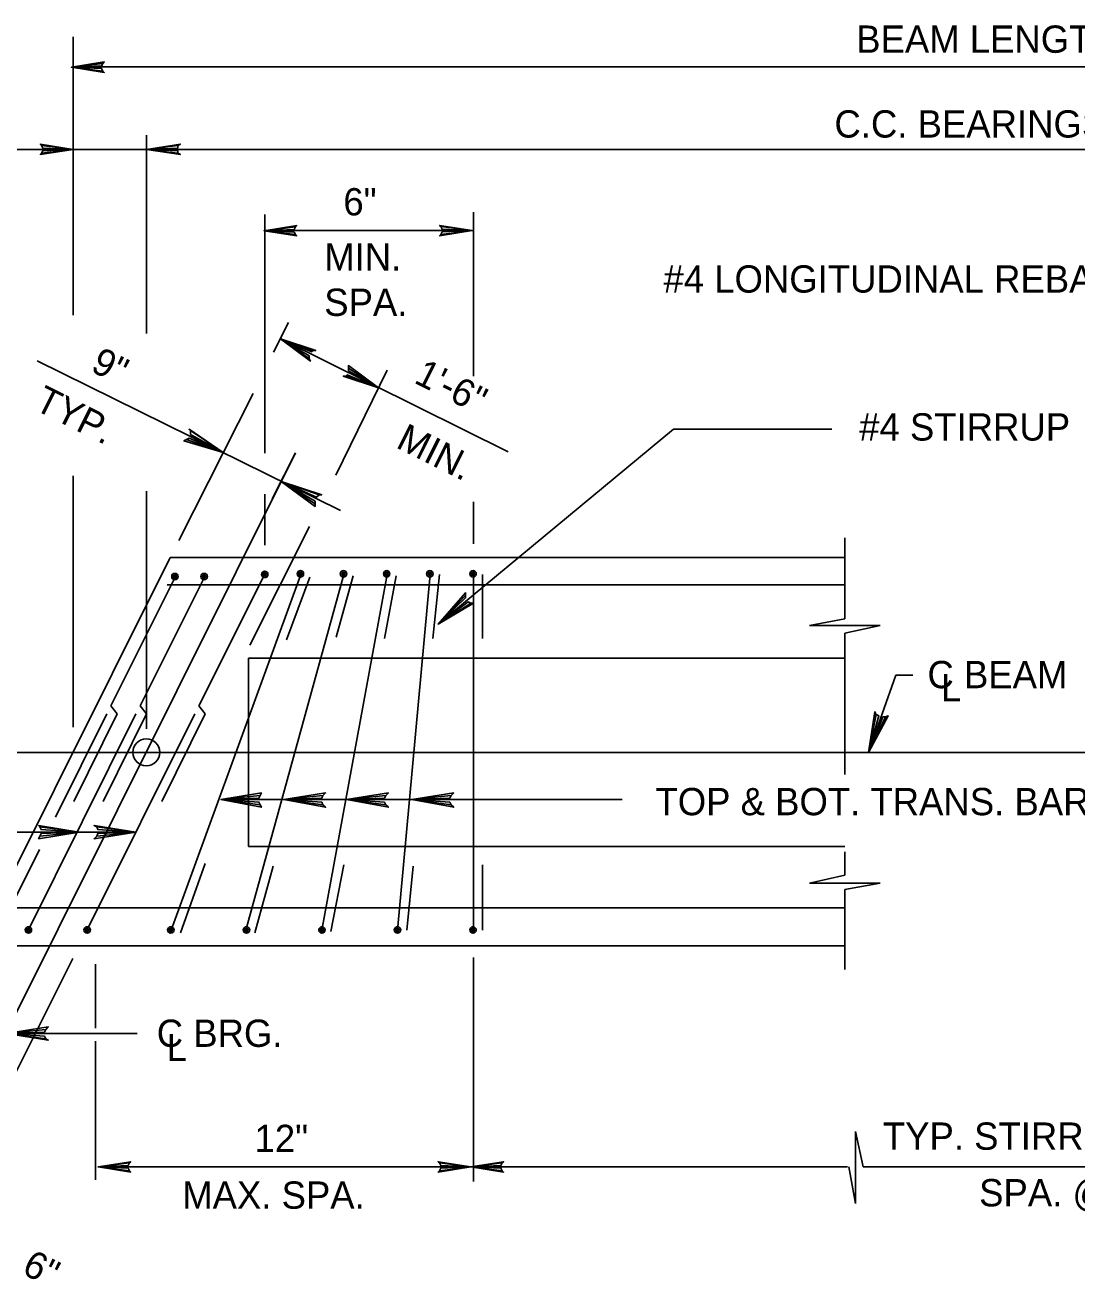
# Model space of a CAD drawing. Extents: x 642009 to 642864, y 298232 to 300014.
# Drawn here: x 642566 to 642681.6, y 299703.5 to 299841.4 of the extents above; entities that cross this region are included whole.
import ezdxf

# ---------------------------------------------------------------- set-up
doc = ezdxf.new("R2010")
doc.units = 0
doc.layers.add('2', color=7, linetype='Continuous')

msp = doc.modelspace()

# ---------------------------------------------------------------- linework, layer by layer
at = {"layer": '2'}
for p, q in [((642571.23, 299840.13), (642571.23, 299809.55)), ((642571.23, 299836.82), (642772.99, 299836.82)), ((642579.29, 299829.34), (642579.29, 299807.53)), ((642533.37, 299827.76), (642571.96, 299827.76)), ((642571.96, 299827.76), (642579.29, 299827.76)), ((642579.29, 299827.76), (642763.44, 299827.76)), ((642592.3, 299794.39), (642592.3, 299820.59)), ((642615.23, 299802.83), (642615.23, 299820.85)), ((642592.3, 299818.83), (642615.11, 299818.83)), ((642593.27, 299805.46), (642594.91, 299808.72)), ((642594.02, 299806.95), (642619.04, 299794.51)), ((642567.3, 299804.54), (642589.79, 299793.41)), ((642600.11, 299791.95), (642605.77, 299803.51)), ((642582.85, 299784.77), (642591.02, 299800.94)), ((642637.23, 299797), (642611.35, 299775.58)), ((642654.61, 299797), (642637.23, 299797)), ((642563.05, 299729.01), (642595.68, 299794.41)), ((642593.13, 299789.35), (642595.68, 299794.41)), ((642589.79, 299793.41), (642600.63, 299788.07)), ((642571.23, 299791.88), (642571.23, 299764.25)), ((642594.1, 299791.25), (642597.69, 299789.53)), ((642579.29, 299790.2), (642579.29, 299764.09)), ((642592.3, 299784.25), (642592.3, 299789.85)), ((642597.69, 299790.1), (642597.69, 299790.1)), ((642615.23, 299784.4), (642615.23, 299789.04)), ((642590.65, 299773.28), (642597.23, 299786.33)), ((642656.06, 299776.16), (642656.06, 299785.07)), ((642560.61, 299740.22), (642581.91, 299782.91)), ((642656.06, 299782.91), (642581.91, 299782.91)), ((642582.46, 299780.75), (642575.39, 299766.59)), ((642585.68, 299780.75), (642578.61, 299766.59)), ((642596.26, 299781.04), (642582.03, 299741.94)), ((642582.46, 299780.75), (642582.46, 299780.75)), ((642582.46, 299780.75), (642582.46, 299780.75)), ((642592.27, 299781.01), (642585.07, 299766.59)), ((642585.68, 299780.75), (642585.68, 299780.75)), ((642585.68, 299780.75), (642585.68, 299780.75)), ((642601, 299781.04), (642590.22, 299741.94)), ((642592.33, 299780.99), (642592.33, 299780.99)), ((642592.33, 299780.99), (642592.33, 299780.99)), ((642597.26, 299780.76), (642594.68, 299773.86)), ((642596.26, 299781.04), (642596.26, 299781.04)), ((642596.26, 299781.04), (642596.26, 299781.04)), ((642596.26, 299781.04), (642596.26, 299781.04)), ((642605.74, 299781.04), (642598.56, 299741.94)), ((642602.01, 299780.9), (642600.14, 299774.14)), ((642601, 299781.04), (642601, 299781.04)), ((642601, 299781.04), (642601, 299781.04)), ((642601, 299781.04), (642601, 299781.04)), ((642601, 299781.04), (642601, 299781.04)), ((642606.75, 299780.9), (642605.46, 299774)), ((642605.74, 299781.04), (642605.74, 299781.04)), ((642605.74, 299781.04), (642605.74, 299781.04)), ((642605.74, 299781.04), (642605.74, 299781.04)), ((642605.74, 299781.04), (642605.74, 299781.04)), ((642605.74, 299781.04), (642605.74, 299781.04)), ((642610.49, 299781.04), (642606.89, 299741.94)), ((642610.49, 299781.04), (642610.49, 299781.04)), ((642610.49, 299781.04), (642610.49, 299781.04)), ((642610.49, 299781.04), (642610.49, 299781.04)), ((642610.49, 299781.04), (642610.49, 299781.04)), ((642610.49, 299781.04), (642610.49, 299781.04)), ((642610.49, 299781.04), (642610.49, 299781.04)), ((642611.49, 299781.04), (642610.78, 299774)), ((642615.23, 299741.94), (642615.23, 299781.04)), ((642615.23, 299781.04), (642615.23, 299781.04)), ((642615.23, 299781.04), (642615.23, 299781.04)), ((642615.23, 299781.04), (642615.23, 299781.04)), ((642615.23, 299781.04), (642615.23, 299781.04)), ((642615.23, 299781.04), (642615.23, 299781.04)), ((642615.23, 299781.04), (642615.23, 299781.04)), ((642615.23, 299781.04), (642615.23, 299781.04)), ((642616.24, 299774), (642616.24, 299781.04)), ((642656.06, 299779.89), (642581.59, 299779.89)), ((642656.06, 299776.16), (642652.18, 299775.44)), ((642659.94, 299775.44), (642652.18, 299775.44)), ((642659.94, 299775.44), (642656.06, 299774.58)), ((642656.06, 299759.05), (642656.06, 299774.58)), ((642656.06, 299771.84), (642590.51, 299771.84)), ((642590.51, 299751.14), (642590.51, 299771.84)), ((642661.66, 299769.98), (642658.64, 299761.49)), ((642663.53, 299769.98), (642661.66, 299769.98)), ((642575.39, 299766.59), (642576.08, 299765.71)), ((642578.61, 299766.59), (642579.3, 299765.71)), ((642585.07, 299766.59), (642585.76, 299765.71)), ((642578.15, 299765.72), (642566.33, 299741.97)), ((642574.93, 299765.72), (642569.29, 299754.37)), ((642576.08, 299765.71), (642571.32, 299756.08)), ((642584.61, 299765.72), (642572.79, 299741.97)), ((642579.3, 299765.71), (642574.53, 299756.08)), ((642585.76, 299765.71), (642580.99, 299756.08)), ((642671.29, 299761.49), (642563.68, 299761.49)), ((642571.96, 299761.49), (642571.96, 299761.49)), ((642579.29, 299761.49), (642579.29, 299761.49)), ((642671.29, 299761.49), (642791.33, 299761.49)), ((642594.39, 299756.32), (642587.49, 299756.32)), ((642601.29, 299756.32), (642594.39, 299756.32)), ((642608.48, 299756.32), (642601.29, 299756.32)), ((642615.38, 299756.32), (642608.48, 299756.32)), ((642631.57, 299756.32), (642615.38, 299756.32)), ((642577.71, 299752.72), (642530.85, 299752.72)), ((642567.53, 299750.83), (642563.12, 299741.97)), ((642656.06, 299751.14), (642590.51, 299751.14)), ((642656.06, 299747.98), (642656.06, 299750.57)), ((642585.76, 299749.28), (642583.03, 299741.66)), ((642593.24, 299748.99), (642591.23, 299741.66)), ((642601, 299749.13), (642599.56, 299741.8)), ((642608.62, 299748.99), (642607.9, 299741.94)), ((642616.24, 299741.94), (642616.24, 299749.13)), ((642656.06, 299747.98), (642652.18, 299747.12)), ((642659.94, 299747.12), (642652.18, 299747.12)), ((642659.94, 299747.12), (642656.06, 299746.4)), ((642656.06, 299737.63), (642656.06, 299746.4)), ((642656.06, 299744.39), (642563.78, 299744.39)), ((642566.33, 299741.94), (642566.33, 299741.94)), ((642566.33, 299741.94), (642566.33, 299741.94)), ((642566.33, 299741.94), (642566.33, 299741.94)), ((642566.33, 299741.94), (642566.33, 299741.94)), ((642566.33, 299741.94), (642566.33, 299741.94)), ((642566.33, 299741.94), (642566.33, 299741.94)), ((642566.33, 299741.94), (642566.33, 299741.94)), ((642566.33, 299741.94), (642566.33, 299741.94)), ((642566.33, 299741.94), (642566.33, 299741.94)), ((642566.33, 299741.94), (642566.33, 299741.94)), ((642566.33, 299741.94), (642566.33, 299741.94)), ((642566.33, 299741.94), (642566.33, 299741.94)), ((642566.33, 299741.94), (642566.33, 299741.94)), ((642572.79, 299741.94), (642572.79, 299741.94)), ((642572.79, 299741.94), (642572.79, 299741.94)), ((642572.79, 299741.94), (642572.79, 299741.94)), ((642572.79, 299741.94), (642572.79, 299741.94)), ((642572.79, 299741.94), (642572.79, 299741.94)), ((642572.79, 299741.94), (642572.79, 299741.94)), ((642572.79, 299741.94), (642572.79, 299741.94)), ((642572.79, 299741.94), (642572.79, 299741.94)), ((642572.79, 299741.94), (642572.79, 299741.94)), ((642572.79, 299741.94), (642572.79, 299741.94)), ((642572.79, 299741.94), (642572.79, 299741.94)), ((642572.79, 299741.94), (642572.79, 299741.94)), ((642572.79, 299741.94), (642572.79, 299741.94)), ((642582.03, 299741.94), (642582.03, 299741.94)), ((642582.03, 299741.94), (642582.03, 299741.94)), ((642582.03, 299741.94), (642582.03, 299741.94)), ((642582.03, 299741.94), (642582.03, 299741.94)), ((642582.03, 299741.94), (642582.03, 299741.94)), ((642582.03, 299741.94), (642582.03, 299741.94)), ((642582.03, 299741.94), (642582.03, 299741.94)), ((642582.03, 299741.94), (642582.03, 299741.94)), ((642582.03, 299741.94), (642582.03, 299741.94)), ((642582.03, 299741.94), (642582.03, 299741.94)), ((642582.03, 299741.94), (642582.03, 299741.94)), ((642582.03, 299741.94), (642582.03, 299741.94)), ((642590.22, 299741.94), (642590.22, 299741.94)), ((642590.22, 299741.94), (642590.22, 299741.94)), ((642590.22, 299741.94), (642590.22, 299741.94)), ((642590.22, 299741.94), (642590.22, 299741.94)), ((642590.22, 299741.94), (642590.22, 299741.94)), ((642590.22, 299741.94), (642590.22, 299741.94)), ((642590.22, 299741.94), (642590.22, 299741.94)), ((642590.22, 299741.94), (642590.22, 299741.94)), ((642590.22, 299741.94), (642590.22, 299741.94)), ((642590.22, 299741.94), (642590.22, 299741.94)), ((642590.22, 299741.94), (642590.22, 299741.94)), ((642598.56, 299741.94), (642598.56, 299741.94)), ((642598.56, 299741.94), (642598.56, 299741.94)), ((642598.56, 299741.94), (642598.56, 299741.94)), ((642598.56, 299741.94), (642598.56, 299741.94)), ((642598.56, 299741.94), (642598.56, 299741.94)), ((642598.56, 299741.94), (642598.56, 299741.94)), ((642598.56, 299741.94), (642598.56, 299741.94)), ((642598.56, 299741.94), (642598.56, 299741.94)), ((642598.56, 299741.94), (642598.56, 299741.94)), ((642598.56, 299741.94), (642598.56, 299741.94)), ((642606.89, 299741.94), (642606.89, 299741.94)), ((642606.89, 299741.94), (642606.89, 299741.94)), ((642606.89, 299741.94), (642606.89, 299741.94)), ((642606.89, 299741.94), (642606.89, 299741.94)), ((642606.89, 299741.94), (642606.89, 299741.94)), ((642606.89, 299741.94), (642606.89, 299741.94)), ((642606.89, 299741.94), (642606.89, 299741.94)), ((642606.89, 299741.94), (642606.89, 299741.94)), ((642606.89, 299741.94), (642606.89, 299741.94)), ((642615.23, 299741.94), (642615.23, 299741.94)), ((642615.23, 299741.94), (642615.23, 299741.94)), ((642615.23, 299741.94), (642615.23, 299741.94)), ((642615.23, 299741.94), (642615.23, 299741.94)), ((642615.23, 299741.94), (642615.23, 299741.94)), ((642615.23, 299741.94), (642615.23, 299741.94)), ((642615.23, 299741.94), (642615.23, 299741.94)), ((642615.23, 299741.94), (642615.23, 299741.94)), ((642656.06, 299740.22), (642560.61, 299740.22)), ((642556.13, 299708.73), (642571.21, 299738.82)), ((642615.23, 299714.34), (642615.23, 299738.93)), ((642573.69, 299731.16), (642573.69, 299738.21)), ((642563.91, 299730.59), (642578.29, 299730.59)), ((642573.69, 299714.49), (642573.69, 299729.73)), ((642657.21, 299719.81), (642657.21, 299711.9)), ((642657.21, 299719.81), (642658.07, 299715.93)), ((642614.94, 299715.93), (642573.98, 299715.93)), ((642656.34, 299715.93), (642614.94, 299715.93)), ((642656.49, 299715.93), (642657.21, 299711.9)), ((642727.36, 299715.93), (642658.07, 299715.93))]:
    msp.add_line(p, q, dxfattribs=at)
for points in [[(642574.51, 299836.36), (642574.37, 299836.65), (642571.06, 299836.79), (642574.51, 299836.36), (642574.66, 299836.22), (642571.06, 299836.79), (642574.37, 299836.94), (642574.51, 299837.22), (642571.06, 299836.79), (642574.66, 299837.37), (642574.51, 299837.22)], [(642567.78, 299828.19), (642567.92, 299827.91), (642571.23, 299827.76), (642567.78, 299828.19), (642567.63, 299828.34), (642571.23, 299827.76), (642567.92, 299827.62), (642567.78, 299827.33), (642571.23, 299827.76), (642567.63, 299827.19), (642567.78, 299827.33)], [(642582.74, 299827.33), (642582.74, 299827.62), (642579.29, 299827.76), (642582.74, 299827.33), (642583.03, 299827.19), (642579.29, 299827.76), (642582.74, 299827.91), (642582.74, 299828.19), (642579.29, 299827.76), (642583.03, 299828.34), (642582.74, 299828.19)], [(642595.68, 299818.39), (642595.53, 299818.68), (642592.23, 299818.82), (642595.68, 299818.39), (642595.82, 299818.25), (642592.23, 299818.82), (642595.53, 299818.97), (642595.68, 299819.26), (642592.23, 299818.82), (642595.82, 299819.4), (642595.68, 299819.26)], [(642611.66, 299819.27), (642611.81, 299818.98), (642615.11, 299818.83), (642611.66, 299819.27), (642611.52, 299819.41), (642615.11, 299818.83), (642611.81, 299818.69), (642611.66, 299818.4), (642615.11, 299818.83), (642611.52, 299818.26), (642611.66, 299818.4)], [(642597.18, 299804.79), (642597.18, 299805.08), (642594.02, 299806.95), (642597.18, 299804.79), (642597.32, 299804.5), (642594.02, 299806.95), (642597.47, 299805.51), (642597.61, 299805.65), (642594.02, 299806.95), (642597.9, 299805.65), (642597.61, 299805.65)], [(642601.5, 299803.71), (642601.5, 299803.43), (642604.81, 299801.56), (642601.5, 299803.71), (642601.5, 299804), (642604.81, 299801.56), (642601.36, 299803), (642601.21, 299802.85), (642604.81, 299801.56), (642600.93, 299802.85), (642601.21, 299802.85)], [(642584.14, 299796.87), (642584.14, 299796.44), (642587.73, 299794.43), (642584.14, 299796.87), (642583.99, 299797.01), (642587.73, 299794.43), (642583.99, 299796.01), (642583.71, 299795.86), (642587.73, 299794.43), (642583.42, 299795.72), (642583.71, 299795.86)], [(642597.84, 299788.81), (642597.84, 299789.09), (642594.1, 299791.25), (642597.84, 299788.81), (642597.84, 299788.52), (642594.1, 299791.25), (642597.98, 299789.53), (642598.27, 299789.81), (642594.1, 299791.25), (642598.56, 299789.81), (642598.27, 299789.81)], [(642614.94, 299777.88), (642614.66, 299778.03), (642611.35, 299775.58), (642614.94, 299777.88), (642615.23, 299777.88), (642611.35, 299775.58), (642614.37, 299778.46), (642614.37, 299778.74), (642611.35, 299775.58), (642614.37, 299779.03), (642614.37, 299778.74)], [(642660.51, 299765.38), (642660.23, 299765.38), (642658.64, 299761.49), (642660.51, 299765.38), (642660.8, 299765.52), (642658.64, 299761.49), (642659.79, 299765.52), (642659.51, 299765.66), (642658.64, 299761.49), (642659.36, 299765.95), (642659.51, 299765.66)], [(642591.8, 299755.74), (642591.66, 299756.03), (642587.49, 299756.32), (642591.8, 299755.74), (642591.94, 299755.46), (642587.49, 299756.32), (642591.66, 299756.46), (642591.8, 299756.75), (642587.49, 299756.32), (642591.94, 299757.04), (642591.8, 299756.75)], [(642598.7, 299755.74), (642598.56, 299756.03), (642594.39, 299756.32), (642598.7, 299755.74), (642598.99, 299755.46), (642594.39, 299756.32), (642598.56, 299756.46), (642598.7, 299756.75), (642594.39, 299756.32), (642598.99, 299757.04), (642598.7, 299756.75)], [(642605.6, 299755.74), (642605.46, 299756.03), (642601.29, 299756.32), (642605.6, 299755.74), (642605.89, 299755.46), (642601.29, 299756.32), (642605.46, 299756.46), (642605.6, 299756.75), (642601.29, 299756.32), (642605.89, 299757.04), (642605.6, 299756.75)], [(642612.79, 299755.74), (642612.64, 299756.03), (642608.48, 299756.32), (642612.79, 299755.74), (642613.08, 299755.46), (642608.48, 299756.32), (642612.64, 299756.46), (642612.79, 299756.75), (642608.48, 299756.32), (642613.08, 299757.04), (642612.79, 299756.75)], [(642567.58, 299753.3), (642567.72, 299753.01), (642571.89, 299752.72), (642567.58, 299753.3), (642567.44, 299753.44), (642571.89, 299752.72), (642567.72, 299752.58), (642567.58, 299752.29), (642571.89, 299752.72), (642567.44, 299752), (642567.58, 299752.29)], [(642573.83, 299753.3), (642573.97, 299753.01), (642578.14, 299752.72), (642573.83, 299753.3), (642573.54, 299753.44), (642578.14, 299752.72), (642573.97, 299752.58), (642573.83, 299752.29), (642578.14, 299752.72), (642573.54, 299752), (642573.83, 299752.29)], [(642568.23, 299730.01), (642568.08, 299730.3), (642563.91, 299730.59), (642568.23, 299730.01), (642568.51, 299729.87), (642563.91, 299730.59), (642568.08, 299730.73), (642568.23, 299731.02), (642563.91, 299730.59), (642568.51, 299731.31), (642568.23, 299731.02)], [(642577.43, 299715.49), (642577.28, 299715.78), (642573.98, 299715.93), (642577.43, 299715.49), (642577.57, 299715.35), (642573.98, 299715.93), (642577.28, 299716.07), (642577.43, 299716.36), (642573.98, 299715.93), (642577.57, 299716.5), (642577.43, 299716.36)], [(642611.49, 299716.36), (642611.64, 299716.07), (642614.94, 299715.93), (642611.49, 299716.36), (642611.35, 299716.5), (642614.94, 299715.93), (642611.64, 299715.78), (642611.49, 299715.49), (642614.94, 299715.93), (642611.35, 299715.35), (642611.49, 299715.49)], [(642618.39, 299715.49), (642618.25, 299715.78), (642614.94, 299715.93), (642618.39, 299715.49), (642618.54, 299715.35), (642614.94, 299715.93), (642618.25, 299716.07), (642618.39, 299716.36), (642614.94, 299715.93), (642618.54, 299716.5), (642618.39, 299716.36)]]:
    msp.add_lwpolyline(points, dxfattribs=at)
for centre, radius in [((642582.43, 299780.81), 0.356), ((642582.43, 299780.81), 0.197), ((642582.43, 299780.81), 0.0936), ((642585.64, 299780.81), 0.356), ((642585.64, 299780.81), 0.197), ((642585.64, 299780.81), 0.0936), ((642592.3, 299781.05), 0.356), ((642592.3, 299781.05), 0.197), ((642592.3, 299781.05), 0.0936), ((642596.22, 299781.11), 0.356), ((642596.22, 299781.11), 0.197), ((642596.22, 299781.11), 0.0936), ((642600.96, 299781.11), 0.356), ((642600.96, 299781.11), 0.197), ((642600.96, 299781.11), 0.0936), ((642605.7, 299781.11), 0.356), ((642605.7, 299781.11), 0.197), ((642605.7, 299781.11), 0.0936), ((642610.45, 299781.11), 0.356), ((642610.45, 299781.11), 0.197), ((642610.45, 299781.11), 0.0936), ((642615.19, 299781.11), 0.356), ((642615.19, 299781.11), 0.197), ((642615.19, 299781.11), 0.0936), ((642579.29, 299761.49), 1.48), ((642566.33, 299741.97), 0.356), ((642566.33, 299741.97), 0.197), ((642566.33, 299741.97), 0.0936), ((642572.79, 299741.97), 0.356), ((642572.79, 299741.97), 0.197), ((642572.79, 299741.97), 0.0936), ((642581.98, 299741.97), 0.356), ((642581.98, 299741.97), 0.197), ((642581.98, 299741.97), 0.0936), ((642590.29, 299741.97), 0.356), ((642590.29, 299741.97), 0.197), ((642590.29, 299741.97), 0.0936), ((642598.59, 299741.97), 0.356), ((642598.59, 299741.97), 0.197), ((642598.59, 299741.97), 0.0936), ((642606.89, 299741.97), 0.356), ((642606.89, 299741.97), 0.197), ((642606.89, 299741.97), 0.0936), ((642615.19, 299741.97), 0.356), ((642615.19, 299741.97), 0.197), ((642615.19, 299741.97), 0.0936)]:
    msp.add_circle(centre, radius, dxfattribs=at)

# ---------------------------------------------------------------- texts
for s, height, p in [('BEAM LENGTH', 2.9998, (642657.3, 299838.38)), ('C.C. BEARINGS', 2.9998, (642654.91, 299829.06)), ('6"', 3, (642600.94, 299820.51)), ('MIN.', 3, (642598.84, 299814.45)), ('#4 LONGITUDINAL REBARS', 2.9998, (642636.12, 299812.02)), ('SPA.', 3, (642598.84, 299809.46)), ('#4 STIRRUP', 3, (642657.63, 299795.76)), ('C BEAM', 3, (642665.13, 299768.54)), ('L', 3, (642666.62, 299767.1)), ('TOP & BOT. TRANS. BARS', 2.9998, (642635.24, 299754.58)), ('C BRG.', 3, (642580.43, 299729.12)), ('L', 3, (642581.51, 299727.55)), ('12"', 3, (642591.18, 299717.56)), ('TYP. STIRRUP REINF.', 2.9998, (642660.23, 299717.81)), ('MAX. SPA.', 3, (642583.23, 299711.33)), ('SPA. @ 12"', 3, (642670.81, 299711.59))]:
    msp.add_text(s, height=height, dxfattribs=at).set_placement(p)
for s, p in [('9"', (642573.03, 299803.45)), ('1\'-6"', (642608.58, 299802.16)), ('TYP.', (642566.82, 299799.23)), ('MIN.', (642606.6, 299795.05)), ('6"', (642565.48, 299704.25))]:
    msp.add_text(s, height=3, rotation=333.4537, dxfattribs=at).set_placement(p)

doc.saveas('drawing.dxf')
